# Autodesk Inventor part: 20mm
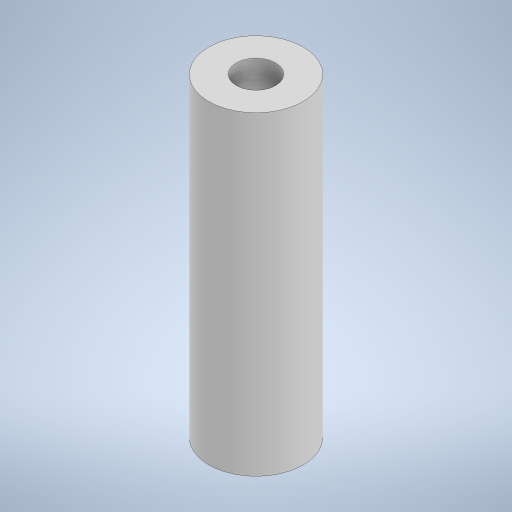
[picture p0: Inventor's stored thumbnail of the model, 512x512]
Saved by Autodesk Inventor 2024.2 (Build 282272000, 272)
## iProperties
Created: 2024-05
Part Number: 20mm
Material: Generic
Document SubType Name: Modeling
Designer: Karsten
Density: 1 g/cm^3
Appearance: Default
Author: Karsten
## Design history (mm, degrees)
sketch "Sketch1"
  geometry: C1 r 1.25 at (0, 0); C2 r 3 at (0, 0); 1 further point
  constraints: 2 centre point, 2 coincident
  dimensions: "d0" = 2.5 diameter of C1; "d1" = 6 diameter of C2
extrude "Extrusion1" new body sketch "Sketch1" distance "d2" = 20; taper "d3" = 0 deg
body "Solid1"
